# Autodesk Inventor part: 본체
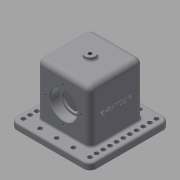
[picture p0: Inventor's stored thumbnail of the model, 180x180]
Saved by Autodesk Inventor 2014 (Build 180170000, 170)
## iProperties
Created: 2018-11
Part Number: 본체
Material: Generic
Document SubType Name: Modeling
Designer: kh
Density: 1 g/cm^3
Appearance: Default
Author: kh
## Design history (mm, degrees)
sketch "스케치1"
  geometry: L1 (-60, -60)-(60, -60); L2 (60, -60)-(60, 60); L3 (60, 60)-(-60, 60); L4 (-60, 60)-(-60, -60); L5 (-60, -60)-(60, 60); L6 (60, -60)-(-60, 60); 1 further point
  constraints: 12 end point, 2 midpoint, 2 parallel, 1 horizontal, 1 perpendicular
  dimensions: "d0" = 120 distance of L3.end L2.end; "d1" = 120 distance of L2.end L1.end
extrude "돌출1" new body sketch "스케치1" distance "d2" = 10; taper "d3" = 0 deg
sketch "스케치2"
  geometry: L1 (-40, -40)-(40, -40); L2 (40, -40)-(40, 40); L3 (40, 40)-(-40, 40); L4 (-40, 40)-(-40, -40); L5 (-40, -40)-(40, 40); L6 (40, -40)-(-40, 40); 1 further point
  constraints: 12 end point, 2 midpoint, 2 parallel, 1 horizontal, 1 perpendicular
  dimensions: "d4" = 80 distance of L3.end L2.end; "d5" = 80 distance of L2.end L1.end
extrude "돌출2" join sketch "스케치2" distance "d6" = 80; taper "d7" = 0 deg
sketch "스케치3"
  geometry: C1 r 7.5 at (0, 0); 1 further point
  constraints: 1 centre point, 1 coincident
  dimensions: "d8" = 7.5 radius of C1
extrude "돌출3" join sketch "스케치3" distance "d9" = 5; taper "d10" = 0 deg
sketch "스케치4"
  geometry: L1 (-23, -30)-(23, -30); L2 (23, -30)-(23, 30); L3 (23, 30)-(-23, 30); L4 (-23, 30)-(-23, -30); L5 (-23, -30)-(23, 30); L6 (23, -30)-(-23, 30); 1 further point
  constraints: 12 end point, 2 midpoint, 2 parallel, 1 horizontal, 1 perpendicular
  dimensions: "d11" = 46 distance of L3.end L2.end; "d12" = 60 distance of L2.end L1.end
extrude "돌출4" cut sketch "스케치4" distance "d13" = 80; taper "d14" = 0 deg
sketch "스케치5"
  geometry: L1 (-40, 10)-(-40, 90) reference; L2 (40, 10)-(40, 90) reference; L3 (-40, 68)-(-26, 68); L4 (-26, 68)-(-26, 64.5); L5 (-26, 64.5)-(26, 64.5); L6 (26, 64.5)-(26, 68); L7 (26, 68)-(40, 68); L8 (-40, 48)-(40, 48); L9 (-23, 0)-(-23, 80) reference; L10 (0, 0)-(0, 94.541); L11 (-40, 68)-(-40, 48); L12 (40, 68)-(40, 48)
  constraints: 18 end point, 4 point on line, 3 collinear, 3 perpendicular, 2 parallel, 1 horizontal, 2 other
  dimensions: "d15" = 48 distance from line of L10.start L8; "d16" = 33 diameter of L5 L8; "d17" = 40 diameter of L7 L8; "d18" = 14 distance of L3.start L3.end
revolve "회전1" sketch "스케치5" stored, may be unused: angle "d19" = 90 deg
sketch "스케치6" dims "d20" = 26
  geometry: L1 (-38, 40)-(-38, 66); C1 r 20 at (-38, 40) reference; 2 further points
  constraints: 2 coincident, 2 end point, 1 vertical, 1 vertical alignment, 2 other
hole "구멍1" sketch "스케치6" at (-38, 66) diameter "d21" = 3.459; stored, may be unused: countersink angle "d25" = 90 deg, drill point angle "d27" = 118 deg; dims "d22" = 8, "d23" = 4, "d24" = 2, "d26" = 10
hole "구멍2" diameter "d33" = 5.459; stored, may be unused: countersink angle "d37" = 90 deg, drill point angle "d39" = 118 deg; dims "d31" = 10, "d32" = 10, "d34" = 15, "d35" = 4, "d36" = 2, "d38" = 10
fillet "모깎기1" dims "d40" = 10
sketch "스케치7"
  geometry: A1 r 10 centre (-50, 50) between (-50, 60) and (-60, 50) reference; 2 further points
  constraints: 1 coincident
hole "구멍3" sketch "스케치7" at (-50, 50) diameter "d41" = 6.6; stored, may be unused: countersink angle "d45" = 90 deg, drill point angle "d47" = 118 deg; dims "d42" = 15, "d43" = 4, "d44" = 2, "d46" = 10
fillet "모깎기2" dims "d54" = 3
fillet "모깎기3" dims "d55" = 3
fillet "모깎기4" dims "d56" = 8
fillet "모깎기5" dims "d57" = 8
fillet "모깎기6" dims "d58" = 3
fillet "모깎기7" dims "d59" = 3
fillet "모깎기8" dims "d60" = 0.6
sketch "스케치8"
  geometry: L1 (74.887, -51.602)-(25.113, -51.602); L2 (25.113, -51.602)-(25.113, -44.398); L3 (25.113, -44.398)-(74.887, -44.398); L4 (74.887, -44.398)-(74.887, -51.602); L5 (74.887, -51.602)-(25.113, -44.398); L6 (25.113, -51.602)-(74.887, -44.398); L7 (50, 0)-(50, -93.783); L8 (100, 0)-(0, 0) reference; L9 (42.5, -95)-(57.5, -95) reference; 5 further points
  constraints: 6 end point, 5 midpoint, 5 point on line, 1 parallel, 2 other
  dimensions: "d61" = 48 distance of L7.start point (50, -48)
feature "엠보싱1" sketch "스케치8" dims "d0" = 120, "d1" = 120, "d62" = 0.5, "d63" = 0
chamfer "모따기1" distance "d64" = 1; stored, may be unused: second distance "d65" = 2, angle "d66" = 45 deg
fillet "모깎기9" dims "d67" = 3
node "솔리드1"
pattern_circular "원형 패턴1" dims angle "d29" = 360 deg
mirror "대칭1"
pattern_linear "직사각형 패턴1" dims "d50" = 10
mirror "대칭2"
pattern_linear "직사각형 패턴2" dims "d53" = 25
mirror "대칭3"
